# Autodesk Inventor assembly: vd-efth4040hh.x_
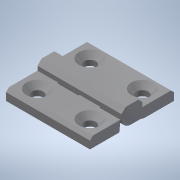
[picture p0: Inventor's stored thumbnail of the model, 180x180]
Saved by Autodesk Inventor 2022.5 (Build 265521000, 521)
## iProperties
Created: 2019-12
Part Number: vd-efth4040hh.x_
Material: 一般
Document SubType Name: Assembly
Designer: ImaoCorp
Sending System: SOLIDWORKS 2018-2018316
MC: AMD64
MC_MODEL: Intel64 Family 6 Model 60 Stepping 3, GenuineIntel
OS: Windows_NT
FRU: Parasolid Version 30.0, build 310,  6- 8-2018
FORMAT: text
GUISE: transmit
KEY: vd-efth4040hh
FILE: vd-efth4040hh.x_t
DATE: Wed Dec 11 13:23:55 2019
Author: ImaoCorp
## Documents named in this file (4)
- X:\14_SW2022-Inv2022\00_全2023-1023新製品(TCC)まで\v\vd-efth4040hh\VD-EFTH4040HH.iam
- X:\14_SW2022-Inv2022\00_全2023-1023新製品(TCC)まで\v\vd-efth4040hh\vd-efth4040hh_01.ipt
- X:\14_SW2022-Inv2022\00_全2023-1023新製品(TCC)まで\v\vd-efth4040hh\vd-efth4040hh_02.ipt
- X:\14_SW2022-Inv2022\00_全2023-1023新製品(TCC)まで\v\vd-efth4040hh\vd-efth4040hh_03.ipt
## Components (3 placed, 3 different names)
1. vd-efth4040hh_01
2. vd-efth4040hh_02
3. vd-efth4040hh_03
